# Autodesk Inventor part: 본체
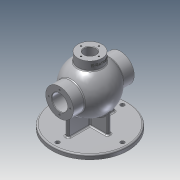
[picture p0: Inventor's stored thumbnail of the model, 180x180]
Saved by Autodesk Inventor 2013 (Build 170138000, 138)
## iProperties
Created: 2020-08
Part Number: 본체
Material: 알루미늄 6061
Document SubType Name: Modeling
Designer: user
Density: 1 g/cm^3
Author: user
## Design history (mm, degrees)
sketch "스케치1"
  geometry: L1 (38.52, -36.403)-(-38.52, 36.403); A1 r 53 centre (0, 0) between (38.52, -36.403) and (-38.52, 36.403); 1 further point
  constraints: 2 end point, 2 point on circle, 1 centre point, 1 coincident, 1 midpoint
  dimensions: "d0" = 106 diameter of A1
revolve "회전1" sketch "스케치1" stored, may be unused: angle "d1" = 90 deg
sketch "스케치2"
  geometry: L1 (31.985, -28.74)-(-31.985, 28.74); A1 r 43 centre (0, 0) between (31.985, -28.74) and (-31.985, 28.74); 1 further point
  constraints: 2 end point, 2 point on circle, 1 centre point, 1 coincident, 1 midpoint
  dimensions: "d2" = 86 diameter of A1
revolve "회전2" sketch "스케치2" stored, may be unused: angle "d3" = 90 deg
node "작업 평면1"
sketch "스케치3"
  geometry: C1 r 31 at (0, 0); 1 further point
  constraints: 1 centre point, 1 coincident
  dimensions: "d5" = 62 diameter of C1
extrude "돌출1" join sketch "스케치3" stored distance "d6" = 10; taper "d7" = 0 deg
node "작업 평면2"
sketch "스케치7"
  geometry: C1 r 85 at (0, 0); 1 further point
  constraints: 1 centre point, 1 coincident
  dimensions: "d18" = 170 diameter of C1
extrude "돌출5" join sketch "스케치7" distance "d19" = 10; taper "d20" = 0 deg
sketch "스케치8"
  geometry: L1 (-4, 43)-(4, 43); L2 (4, 43)-(4, -43); L3 (4, -43)-(-4, -43); L4 (-4, -43)-(-4, 43); C1 r 85 at (0, 0) reference
  constraints: 8 end point, 2 parallel, 1 horizontal, 1 perpendicular
  dimensions: "d21" = 8 distance of L1.start L1.end; "d23" = 86 distance of L1.end L2.end; "d24" = 4 distance from line of C1.centre L4; "d25" = 43 distance from line of C1.centre L1
extrude "돌출6" join sketch "스케치8" stored distance "d26" = 10; taper "d27" = 0 deg
sketch "스케치9"
  geometry: L1 (-52, 4)-(52, 4); L2 (52, 4)-(52, -4); L3 (52, -4)-(-52, -4); L4 (-52, -4)-(-52, 4); C1 r 85 at (0, 0) reference
  constraints: 8 end point, 2 parallel, 1 horizontal, 1 perpendicular
  dimensions: "d28" = 8 distance of L1.end L2.end; "d30" = 104 distance of L2.end L3.end; "d31" = 4 distance from line of C1.centre L1; "d32" = 52 distance from line of C1.centre L2
extrude "돌출7" join sketch "스케치9" stored distance "d33" = 10; taper "d34" = 0 deg
node "작업 평면3"
sketch "스케치10"
  geometry: C1 r 27 at (0, 0); 1 further point
  constraints: 1 centre point, 1 coincident
  dimensions: "d36" = 54 diameter of C1
extrude "돌출8" join sketch "스케치10" stored distance "d37" = 10; taper "d38" = 0 deg
sketch "스케치11"
  geometry: C1 r 27 at (0, 0) reference; C2 r 13 at (0, 0)
  constraints: 1 centre point, 1 coincident
  dimensions: "d39" = 26 diameter of C2
extrude "돌출9" cut sketch "스케치11" distance "d40" = 100; taper "d41" = 0 deg
sketch "스케치14" dims "d49" = 145
  geometry: C1 r 85 at (0, 0) reference; 2 further points
  constraints: 2 vertical alignment, 1 coincident, 2 other
hole "구멍1" sketch "스케치14" at (0, 72.5) diameter "d50" = 9; stored, may be unused: countersink angle "d54" = 90 deg, drill point angle "d56" = 118 deg; dims "d51" = 6, "d52" = 4, "d53" = 2, "d55" = 8
sketch "스케치16" dims "d71" = 40
  geometry: C1 r 13 at (0, 0) reference; C2 r 27 at (0, 0) reference; 2 further points
  constraints: 2 vertical alignment, 1 coincident, 2 other
hole "구멍3" sketch "스케치16" at (0, 20) diameter "d72" = 3.242; stored, may be unused: countersink angle "d76" = 90 deg, drill point angle "d78" = 118 deg; dims "d73" = 12, "d74" = 4, "d75" = 2, "d77" = 15
node "작업 평면4"
sketch "스케치18"
  geometry: L1 (-27, 65)-(27, 65) reference; 3 further points
  constraints: 1 midpoint, 1 vertical alignment, 1 other
  dimensions: "d94" = 9 distance from line of point (0, 56) L1
feature "엠보싱1" sketch "스케치18" dims "d0" = 106, "d18" = 170, "d95" = 0.5, "d96" = 0
fillet "모깎기1" dims "d97" = 3
fillet "모깎기2" dims "d98" = 3
fillet "모깎기3" dims "d99" = 3
fillet "모깎기4" dims "d100" = 3
fillet "모깎기5" dims "d101" = 3
chamfer "모따기1" distance "d102" = 1; stored, may be unused: second distance "d103" = 2, angle "d104" = 45 deg
sketch "스케치19"
  geometry: C1 r 31 at (0, 0) reference; C2 r 17.5 at (0, 0)
  constraints: 1 centre point, 1 coincident
  dimensions: "d105" = 35 diameter of C2
extrude "돌출12" cut sketch "스케치19" distance "d106" = 16; taper "d107" = 0 deg
sketch "스케치20"
  geometry: C1 r 17.5 at (0, 0) reference; C2 r 18.5 at (0, 0)
  constraints: 1 centre point, 1 coincident
  dimensions: "d108" = 37 diameter of C2
extrude "돌출13" cut sketch "스케치20" distance "d109" = 1.75; taper "d110" = 0 deg
sketch "스케치21"
  geometry: C1 r 18.5 at (0, 0) reference; C2 r 17.5 at (0, 0)
  constraints: 1 centre point, 1 coincident
  dimensions: "d111" = 35 diameter of C2
extrude "돌출14" cut sketch "스케치21" stored distance "d112" = 1.75; taper "d113" = 0 deg
sketch "스케치22" dims "d114" = 48
  geometry: C1 r 17.5 at (0, 0) reference; C2 r 31 at (0, 0) reference; 2 further points
  constraints: 2 vertical alignment, 1 coincident, 2 other
hole "구멍5" sketch "스케치22" at (0, 24) diameter "d115" = 3.242; stored, may be unused: countersink angle "d119" = 90 deg, drill point angle "d121" = 118 deg; dims "d116" = 12, "d117" = 4, "d118" = 2, "d120" = 15
chamfer "모따기2" distance "d125" = 1; stored, may be unused: second distance "d126" = 2, angle "d127" = 45 deg
node "솔리드1"
mirror "대칭1"
pattern_circular "원형 패턴1" dims angle "d58" = 360 deg
pattern_circular "원형 패턴3" dims angle "d80" = 360 deg
pattern_circular "원형 패턴5" dims angle "d123" = 360 deg
mirror "대칭3"
other parameters: "d4" = 68, "d17" = -85, "d35" = 65, "d93" = 29
